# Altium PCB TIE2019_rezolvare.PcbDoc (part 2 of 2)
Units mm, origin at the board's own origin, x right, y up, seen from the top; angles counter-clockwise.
Board outline 267 x 129 mm, 8 copper layers (Signal 1, GND/Signal 2, GND 3, Signal 4, GND, Power/Signal 6, GND 7, Signal 8), stack 1.597 mm thick; 97 components, 82 nets, 657 pads, 352 vias.
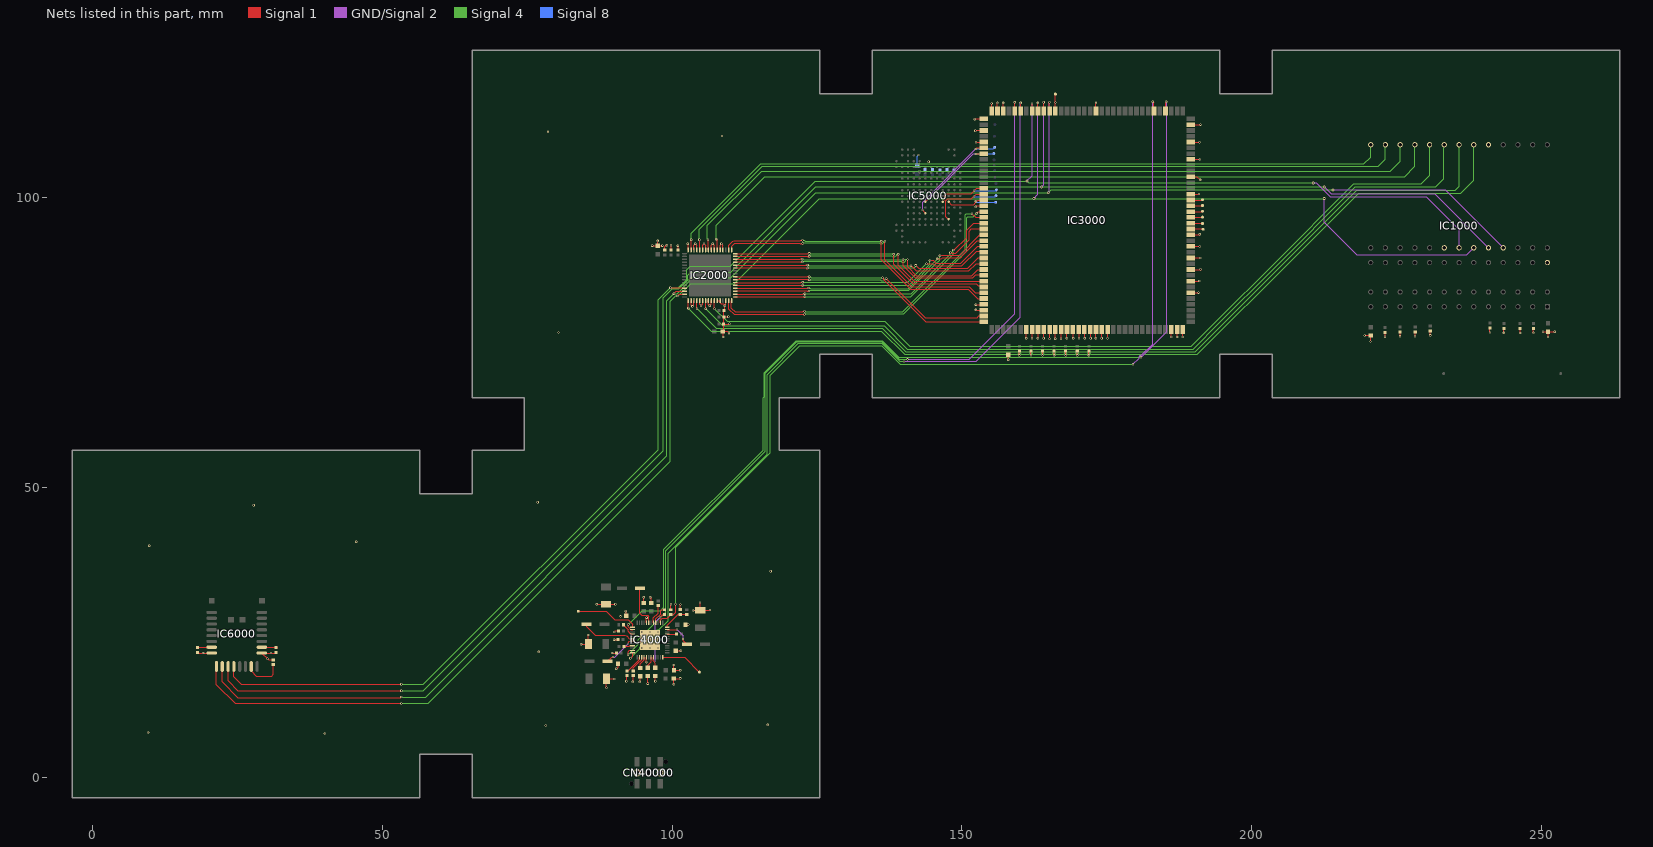
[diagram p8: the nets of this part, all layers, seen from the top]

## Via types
v1: diameter 0.4, hole 0.2, Signal 1 to Signal 8, 276 vias
v2: diameter 0.6, hole 0.3, Signal 1 to Signal 8, 49 vias
v3: diameter 0.325, hole 0.125, Signal 1 to GND/Signal 2, 9 vias
v4: diameter 0.5, hole 0.2, GND/Signal 2 to GND 7, 9 vias
v5: diameter 0.4, hole 0.2, Signal 1 to Signal 8, tented both sides, 9 vias

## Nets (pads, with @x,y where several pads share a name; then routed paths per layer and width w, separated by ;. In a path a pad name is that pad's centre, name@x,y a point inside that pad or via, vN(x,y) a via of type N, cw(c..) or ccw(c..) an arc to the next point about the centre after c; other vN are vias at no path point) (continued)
eMMC_DATA5: IC3000.83 IC5000.K8 TP_D5.1 | length 12.4
  Signal 1 w0.09: IC5000.K8@146.7,99.35 147.125,99.775 147.125,100.5 147.35,100.725 151.625,100.725 152.12,101.22 v1@152.123,101.223 ; v1(152.095,101.25) v1@152.123,101.223 ; IC3000.83@153.775,101.65 152.55,101.65 v1@152.123,101.223
  Signal 8 w0.09: v1(152.095,101.25) 152.095,101.244 155.778,101.244 TP_D5.1@155.931,101.397
eMMC_DATA6: IC3000.84 IC5000.N9 TP_D6.1 | length 14.2
  Signal 1 w0.09: IC5000.N9@147.7,96.35 147.25,96.8 147.25,99.55 147.525,99.825 151.65,99.825 152.475,100.65 IC3000.84@153.775,100.65
  Signal 8 w0.09: v1(152.07,100.254) 155.727,100.254 TP_D6.1@155.88,100.406
eMMC_DATA7: IC3000.85 IC5000.K9 TP_D7.1 | length 10.4
  Signal 1 w0.09: IC5000.K9@147.7,99.35 148.2,98.85 152.025,98.85 152.4,99.225 152.4,99.263 v1@152.493,99.357 ; v1(152.4,99.45) v1@152.493,99.357 ; IC3000.85@153.775,99.65 152.787,99.65 v1@152.493,99.357
  Signal 8 w0.09: v1(152.4,99.45) 152.4,99.263 TP_D7.1@155.829,99.263
eMMC_DS: IC3000.77 IC5000.K5 TP_DS.1 | length 16.6
  Signal 1 w0.09: IC5000.K5@143.7,99.35 v3(144.15,99.8) ; v1@152.35,107.6 152.4,107.65 IC3000.77@153.775,107.65
  GND/Signal 2 w0.09: v3(144.15,99.8) 151.95,107.6 v1@152.35,107.6
  Signal 8 w0.09: v1(152.4,107.594) 155.423,107.594 TP_DS.1@155.499,107.671
eMMC_RST: IC3000.76 IC5000.M5 TP_RST.1 | length 20
  Signal 1 w0.09: v3(143.2,97.9) 143.2,97.85 IC5000.M5@143.7,97.35 ; v1@152.4,108.5 152.55,108.65 IC3000.76@153.775,108.65
  GND/Signal 2 w0.09: v3(143.2,97.9) 143.2,99.3 v1@152.4,108.5
  Signal 8 w0.09: v1(152.4,108.458) 155.372,108.458 TP_RST.1@155.651,108.737
FRAME_CLK_N: IC2000.24 IC3000.106 | length 46.3
  Signal 1 w0.2: IC2000.24@110.899,86.415 110.934,86.38 110.954,86.4 123.33,86.4 123.43,86.5 123.65,86.5 v1(123.65,86.4) ; v1(136.3,86.235) 136.52,86.015 136.52,85.922 143.772,78.67 153.755,78.67 IC3000.106@153.775,78.65
  Signal 4 w0.09: v1(123.65,86.4) 123.675,86.375 123.847,86.375 123.987,86.235 v1(136.3,86.235)
FRAME_CLK_P: IC2000.23 IC3000.105 | length 46.1
  Signal 1 w0.2: IC2000.23@110.899,85.915 110.934,85.95 111.113,85.95 111.123,85.96 111.388,85.96 111.398,85.97 123.33,85.97 123.43,85.87 123.65,85.87 v1(123.65,85.9) ; v1(136.95,86.1) 143.7,79.35 152.625,79.35 152.925,79.65 IC3000.105@153.775,79.65
  Signal 4 w0.09: v1(123.65,85.9) 123.675,85.925 123.844,85.925 123.854,85.915 135.948,85.915 136.103,85.76 136.497,85.76 136.775,86.038 136.775,86.1 v1(136.95,86.1)
GND: C1001.1 C1002.1 C1003.1 C1004.1 C1005.1 C1101.1 C1102.1 C1103.1 C1104.1 C1105.1 C2001.1 C2002.1 C2003.1 C2004.1 C2101.1 C2102.1 C2103.1 C2104.1 C3000.2 C3001.2 C3002.2 C3003.2 C3004.2 C3005.2 C3006.2 C3007.2 C4001.1 C4002.1 C4003.1 C4004.2 C4005.2 C4006.1 C4007.1 C4008.1 C4009.1 C4010.2 C4011.1 C4012.2 C4013.1 C4014.2 C4015.1 C4016.2 C4017.1 C4019.1 C5001.2 C5002.2 C5003.2 C5004.1 C5005.1 C5006.1 C6001.1 C6002.1 C6003.1 CN40000.1 CN40000.3 IC1000.D1 IC1000.E8 IC1000.M5 IC2000.2 IC2000.3 IC2000.5 IC2000.6 IC2000.8 IC2000.9 IC2000.11 IC2000.12 IC2000.14 IC2000.36 IC2000.37 IC2000.39 IC2000.40 IC2000.42 IC2000.43 IC2000.45 IC2000.46 IC2000.48 IC3000.6 IC3000.8 IC3000.10 IC3000.12 IC3000.14 IC3000.16 IC3000.23 IC3000.26 IC3000.29 IC3000.32 IC3000.35 IC3000.52 IC3000.59 IC3000.68 IC3000.69 IC3000.70 IC3000.71 IC3000.73 IC3000.75 IC3000.86 IC3000.103 IC3000.104 IC3000.113 IC3000.114 IC3000.115 IC3000.116 IC3000.117 IC3000.118 IC3000.119 IC3000.120 IC3000.121 IC3000.122 IC3000.123 IC3000.124 IC3000.125 IC3000.126 IC3000.127 IC3000.138 IC3000.139 IC3000.140 IC4000.20 IC4000.41 IC4000.49 IC6000.8 IC6000.17 R4002.1 R4003.1 R4004.1 TH4000.1 TP3007.1 | length 154.5
  Signal 1 w0.1: C6003.1@18.3,21.58 18.38,21.5 v1(19.1,21.5) IC6000.8@20.575,21.5 ; C6002.1@31.2,20.32 30.38,20.32 v1(30.2,20.5) 29.225,21.475 IC6000.17@29.225,21.5 v1(30.8,21.5) 31.58,21.5 31.6,21.48 C6001.1@31.7,21.58 ; v1@84.4,23 84.45,23.05 C4013.1@85.575,23.05 v1@85.575,24.525 ; v1(87,29.9) C4017.1@88.6,29.9 v1@90.2,29.9 ; v1@88.675,15.525 C4011.1@88.675,17.05 v1@89.95,17.05 ; v1(89.647,21.5) C4009.1@90.38,21.5 ; v1@90,25.1 90.2,25.3 C4010.2@90.76,25.3 ; 90.2,23.8 C4012.2@90.86,23.8 ; v1(90.375,18.785) 90.675,19.085 C4002.1@90.675,19.65 ; C4019.1@91.96,27.8 C4019.1@92.06,27.9 v1@92.06,28.64 ; v1(92.109,16.619) 92.2,16.71 R4002.1@92.2,17.58 ; v1@93.3,16.5 R4003.1@93.3,17.59 ; v1@94.475,16.575 C4008.1@94.475,17.73 ; C4003.1@95.1,30.12 v1@95.1,31.1 ; v1(95.575,19.925) IC4000.41@95.575,20.75 ; IC4000.20@95.575,26.75 95.575,27.575 v1(95.6,27.6) ; v1@95.775,16.225 C4007.1@95.775,17.53 ; 95.775,16.425 v1@95.8,16.4 ; v1@96.2,31.1 96.4,30.9 C4016.2@96.4,30.12 ; v1(96.575,91.775) 96.61,91.74 C2001.1@97.525,91.74 ; v1@97.075,16.625 C4006.1@97.075,17.53 ; v1(97.5,92.6) 97.525,92.575 C2001.1@97.525,91.74 ; v1(98.325,91.775) 98.29,91.74 C2001.1@97.525,91.74 ; C2004.1@98.725,91.005 98.725,91.625 98.95,91.85 v1(99.1,91.85) ; R4004.1@99.775,28.96 v1@99.775,29.875 ; C2003.1@99.825,91.005 v1(99.825,91.85) ; v1@100.3,16.1 C4001.1@100.3,17.1 v1@101.4,17.1 ; v1@100.32,19.38 C4005.2@100.32,18.5 v1@101.4,18.5 ; C4004.2@100.6,21.88 v1@101.5,21.88 ; v1(101,91.775) 101.025,91.75 C2002.1@101.025,91.005 ; TH4000.1@101.4,29 v1@101.4,29.825 ; C4014.2@102.32,26.4 102.773,26.4 v1(102.773,26.419) ; v1(102.7,92.1) 102.774,92.026 IC2000.48@102.774,91.04 ; IC2000.2@103.274,82.29 103.274,81.526 v1(103.5,81.3) 103.774,81.574 IC2000.3@103.774,82.29 ; v1(103.627,28.819) 103.627,28.85 C4015.1@104.875,28.85 ; IC2000.46@103.774,91.04 103.774,91.874 v1(104,92.1) 104.274,91.826 IC2000.45@104.274,91.04 ; IC2000.5@104.774,82.29 104.774,81.626 v1(105,81.4) 105.274,81.674 IC2000.6@105.274,82.29 ; v1@104.875,30.125 C4015.1@104.875,28.85 ; IC2000.43@105.274,91.04 105.274,91.874 v1(105.5,92.1) 105.774,91.826 IC2000.42@105.774,91.04 ; IC2000.8@106.274,82.29 106.274,81.626 v1(106.5,81.4) 106.774,81.674 IC2000.9@106.774,82.29 ; v1@106.55,28.85 C4015.1@104.875,28.85 ; IC2000.40@106.774,91.04 106.774,91.874 v1(107,92.1) 107.274,91.826 IC2000.39@107.274,91.04 ; IC2000.11@107.774,82.29 IC2000.12@108.274,82.29 108.274,81.903 108.462,81.715 108.849,81.715 109.1,81.465 v1(109.1,81.4) ; IC2000.37@108.274,91.04 108.274,91.874 v1(108.5,92.1) 108.774,91.826 IC2000.36@108.774,91.04 ; v1(108.8,76) 108.8,76.895 C2101.1@108.72,76.975 ; IC2000.14@109.274,82.29 109.274,81.574 109.132,81.432 v1(109.1,81.4) ; v1(109.7,79.5) 109.675,79.475 C2103.1@108.92,79.475 ; v1(109.829,76.689) 109.543,76.975 C2101.1@108.72,76.975 ; v1(109.9,78.3) 109.857,78.257 C2102.1@108.901,78.257 ; v1@152.25,111.65 IC3000.73@153.775,111.65 ; v1@152.3,113.6 152.35,113.65 IC3000.71@153.775,113.65 ; v1(152.384,98.46) 152.574,98.65 IC3000.86@153.775,98.65 ; v1(152.4,80.7) 152.45,80.65 IC3000.104@153.775,80.65 ; v1(152.4,81.6) 153.725,81.6 IC3000.103@153.775,81.65 ; v1(152.424,109.605) 152.424,109.624 152.45,109.65 IC3000.75@153.775,109.65 ; IC3000.70@155.125,115 v1@155.125,116.275 ; v1@156.1,116.4 156.125,116.375 IC3000.69@156.125,115 ; IC3000.68@157.125,115 v1@157.125,116.375 ; v1(158,72.1) C3000.2@158,72.96 ; v1(159.9,72.845) C3001.2@159.9,73.58 ; v1(161.1,75.8) 161.125,75.825 IC3000.113@161.125,77.3 ; v1(161.9,72.845) C3002.2@161.9,73.58 ; v1(162.1,75.8) 162.125,75.825 IC3000.114@162.125,77.3 ; v1(163.1,75.8) 163.125,75.825 IC3000.115@163.125,77.3 ; v1(163.9,72.845) C3003.2@163.9,73.58 ; v1(164.1,75.8) 164.125,75.825 IC3000.116@164.125,77.3 ; v1(165.1,75.7) 165.125,75.725 IC3000.117@165.125,77.2 ; v1(165.9,72.845) C3004.2@165.9,73.58 ; v1(166.1,75.7) 166.125,75.725 IC3000.118@166.125,77.2 ; IC3000.59@166.125,115 166.125,117.925 TP3007.1@166.127,117.927 ; v1(167.1,75.7) 167.125,75.725 IC3000.119@167.125,77.2 ; v1(167.9,72.845) C3005.2@167.9,73.58 ; v1(168.1,75.8) 168.125,75.825 IC3000.120@168.125,77.3 ; v1(169.2,75.8) 169.225,75.825 IC3000.121@169.225,77.3 ; v1(169.9,72.845) C3006.2@169.9,73.58 ; v1(170.2,75.8) 170.225,75.825 IC3000.122@170.225,77.3 ; v1(171.2,75.8) 171.225,75.825 IC3000.123@171.225,77.3 ; v1(171.9,72.845) C3007.2@171.9,73.58 ; v1(172.2,75.8) 172.225,75.825 IC3000.124@172.225,77.3 ; v1(173.1,75.8) 173.125,75.825 IC3000.125@173.125,77.3 ; v1@173.1,116.4 173.125,116.375 IC3000.52@173.125,115 ; v1(174.1,75.8) 174.125,75.825 IC3000.126@174.125,77.3 ; v1(175.1,75.8) 175.125,75.825 IC3000.127@175.125,77.3 ; v1(186.124,76.005) 186.125,76.006 IC3000.138@186.125,77.3 ; v1(187.125,76.025) IC3000.139@187.125,77.3 ; v1(188.1,76) 188.125,76.025 IC3000.140@188.125,77.3 ; IC3000.6@189.475,83.65 v1@190.85,83.65 ; IC3000.8@189.475,85.65 191.05,85.65 v1@191.049,85.651 ; IC3000.10@189.475,87.65 191.25,87.65 v1@191.24,87.66 ; IC3000.12@189.475,89.65 v1@191.15,89.65 ; IC3000.14@189.475,91.65 v1@191.15,91.65 ; IC3000.16@189.475,93.65 v1@191.05,93.65 ; IC3000.23@189.475,100.65 190.85,100.65 v1(190.9,100.7) ; IC3000.26@189.475,103.65 190.55,103.65 191.075,103.125 v1(191.1,103.125) ; IC3000.29@189.475,106.65 v1(191.05,106.65) ; IC3000.32@189.475,109.65 190.95,109.65 v1(191,109.6) ; IC3000.35@189.475,112.65 v1(191.15,112.65) ; v1(219.475,76.275) 220.495,76.275 C1005.1@220.5,76.28 220.5,75.275 v1@220.475,75.25 ; v1(222.975,76.075) 223,76.1 C1004.1@223,76.78 ; C1003.1@225.6,76.88 225.6,76.04 v1@225.623,76.017 ; v1(228.175,76.15) 228.2,76.175 C1002.1@228.2,76.88 ; v1(230.8,76.3) C1001.1@230.8,77.06 ; v1(241.1,76.8) C1104.1@241.1,77.48 ; v1@243.483,76.713 v1(243.5,76.73) C1103.1@243.5,77.48 ; v1(246.3,76.7) C1102.1@246.3,77.48 ; v1(248.6,76.725) C1101.1@248.6,77.48 ; v1(250.235,76.935) C1105.1@251.118,76.935 ; v1(251.118,76.018) C1105.1@251.118,76.935 ; v1(252.265,76.935) C1105.1@251.118,76.935 ; C2101.1@108.72,76.975 108.901,77.156 C2102.1@108.901,78.257 ; C2102.1@108.901,78.257 108.92,78.277 C2103.1@108.92,79.475 ; C2103.1@108.92,79.475 108.92,80.655 108.9,80.675 109.042,80.817 109.042,81.342 v1(109.1,81.4)
  Signal 8 w0.09: C5001.2@142.3,105.59 142.3,107.2 v1(142.5,107.4)
  other v1: 40.1,7.6 9.6,7.8 78.2,9 116.5,9.1 88.677,15.516 100.309,16.119 95.809,16.219 93.209,16.519 94.409,16.519 97.109,16.619 90.009,17.019 101.409,17.119 101.409,18.519 100.309,19.419 77,21.7 101.509,21.899 84.309,23.019 90,23.8 85.509,24.619 90.009,25.119 91.109,27.819 92.009,28.719 106.538,28.928 101.434,29.869 90.209,29.919 99.809,29.919 104.809,30.219 95.109,31.119 96.209,31.119 117,35.6 9.8,40 45.5,40.7 27.8,47 76.8,47.5 220.5,75.25 225.575,76.125 80.4,76.8 190.815,83.668 190.96,85.687 191.163,87.695 191.127,89.635 191.027,91.635 191.027,93.735 144.25,106.25 108.6,110.7 78.6,111.4 152.324,111.605 152.224,113.605 155.124,116.305 156.124,116.405 157.107,116.408 173.124,116.405 166.149,116.468
  other v5: 94.775,22.35 96.175,22.35 97.575,22.35 94.775,23.75 96.175,23.75 97.575,23.75 94.775,25.15 96.175,25.15 97.575,25.15
IMGSEN_DATA0: IC1000.M6 IC2000.1 | length 159.6
  Signal 1 w0.1: IC2000.1@102.774,82.29 102.774,81.026 v1(102.8,81)
  Signal 4 w0.07: v1(102.8,81) 106.773,77.027 125.5,77.027 134.5,77.027 136.079,77.027 140.095,73.011 159.592,73.011 159.761,73.18 160.039,73.18 160.208,73.011 161.592,73.011 161.761,73.18 162.039,73.18 162.208,73.011 163.592,73.011 163.761,73.18 164.039,73.18 164.208,73.011 165.592,73.011 165.761,73.18 166.039,73.18 166.208,73.011 167.592,73.011 167.761,73.18 168.039,73.18 168.208,73.011 169.592,73.011 169.761,73.18 170.039,73.18 170.208,73.011 171.592,73.011 171.761,73.18 172.039,73.18 172.208,73.011 190.613,73.011 194.5,76.898 203.5,85.898 218.415,100.813 236.017,100.813 238.3,103.096 238.3,106.474 IC1000.M6@238.3,109.18
IMGSEN_DATA1: IC1000.M7 IC2000.4 | length 154.9
  Signal 1 w0.1: IC2000.4@104.274,82.29 104.274,80.926 v1(104.3,80.9)
  Signal 4 w0.07: v1(104.3,80.9) 107.64,77.56 125.5,77.56 134.5,77.56 136.232,77.56 140.298,73.494 190.257,73.494 194.5,77.736 203.5,86.736 218.135,101.371 235.077,101.371 235.76,102.054 235.76,105.159 IC1000.M7@235.76,109.18
IMGSEN_DATA2: IC1000.M8 IC2000.7 | length 149.7
  Signal 1 w0.1: IC2000.7@105.774,82.29 105.774,80.926 v1(105.8,80.9)
  Signal 4 w0.07: v1(105.8,80.9) 108.772,77.928 109.324,77.928 109.598,77.928 110.002,77.928 125.5,77.928 134.5,77.928 136.575,77.928 140.603,73.9 189.876,73.9 194.5,78.524 203.5,87.524 217.881,101.905 231.75,101.905 233.147,103.302 233.147,109.107 IC1000.M8@233.22,109.18
IMGSEN_DATA3: IC1000.M9 IC2000.10 | length 145.1
  Signal 1 w0.1: IC2000.10@107.274,82.29 107.274,80.926 v1(107.3,80.9)
  Signal 4 w0.07: v1(107.3,80.9) 109.5,78.7 109.904,78.7 110.3,78.7 125.5,78.7 134.5,78.7 136.692,78.7 141.009,74.383 189.572,74.383 194.5,79.311 203.5,88.311 217.602,102.413 229.26,102.413 230.734,103.886 230.734,109.126 IC1000.M9@230.68,109.18
IMGSEN_DATA4: IC1000.M10 IC2000.38 | length 132.8
  Signal 1 w0.1: v1(107.6,92.9) 107.774,92.726 IC2000.38@107.774,91.04
  Signal 4 w0.1: v1(107.6,92.9) 107.575,92.925 107.575,95.281 115.994,103.7 125.5,103.7 134.5,103.7 140.555,103.7 140.845,103.7 141.555,103.7 141.845,103.7 142.555,103.7 142.845,103.7 142.959,103.7 143.544,103.7 143.555,103.7 143.845,103.7 144.555,103.7 144.845,103.7 145.555,103.7 145.845,103.7 194.5,103.7 203.5,103.7 226.357,103.7 228.14,105.483 IC1000.M10@228.14,109.18
IMGSEN_DATA5: IC1000.M11 IC2000.41 | length 131.2
  Signal 1 w0.1: v1(106.2,92.8) 106.274,92.726 IC2000.41@106.274,91.04
  Signal 4 w0.1: v1(106.2,92.8) 106.1,92.9 106.1,95.254 115.496,104.65 125.5,104.65 134.5,104.65 142.505,104.65 142.555,104.7 142.845,104.7 142.895,104.65 194.5,104.65 203.5,104.65 223.878,104.65 225.6,106.372 IC1000.M11@225.6,109.18
IMGSEN_DATA6: IC1000.M12 IC2000.44 | length 129.5
  Signal 1 w0.1: v1(104.7,92.8) 104.774,92.726 IC2000.44@104.774,91.04
  Signal 4 w0.1: v1(104.7,92.8) 104.65,92.85 104.65,94.592 115.519,105.461 125.5,105.461 134.5,105.461 194.5,105.461 203.5,105.461 221.818,105.461 223.06,106.703 IC1000.M12@223.06,109.18
IMGSEN_DATA7: IC1000.M13 IC2000.47 | length 127.7
  Signal 1 w0.1: IC2000.47@103.274,91.04 103.274,91.799 103.289,91.814 103.28,91.822 103.28,92.78 v1(103.3,92.8)
  Signal 4 w0.1: v1(103.3,92.8) 103.28,92.82 103.28,93.882 115.298,105.9 125.5,105.9 134.5,105.9 144.105,105.9 144.395,105.9 194.5,105.9 203.5,105.9 219.356,105.9 220.52,107.064 IC1000.M13@220.52,109.18
LVDS_D0_N: IC2000.16 IC3000.88 | length 56
  Signal 1 w0.2: IC2000.16@110.274,82.29 110.239,82.255 110.239,81 110.864,80.375 122.505,80.375 122.605,80.475 122.825,80.475 v1(122.825,80.445) ; v1(151.725,97.27) 152.345,96.65 IC3000.88@153.775,96.65
  Signal 4 w0.09: v1(122.825,80.445) 122.915,80.355 139.8,80.355 150.55,91.105 150.55,97.083 150.737,97.27 v1(151.725,97.27)
LVDS_D0_P: IC2000.15 IC3000.87 | length 56.6
  Signal 1 w0.2: IC2000.15@109.774,82.29 109.809,82.255 109.809,80.822 110.686,79.945 122.505,79.945 122.605,79.845 122.825,79.845 v1(122.825,79.945) ; v1(152.55,97.375) 152.825,97.65 IC3000.87@153.775,97.65
  Signal 4 w0.09: v1(122.825,79.945) 122.915,80.035 139.933,80.035 150.8,90.902 150.8,96.6 150.97,96.77 151.945,96.77 v1(152.55,97.375)
LVDS_D1_N: IC2000.18 IC3000.90 | length 48.8
  Signal 1 w0.2: IC2000.18@110.899,83.415 110.934,83.38 110.979,83.425 122.58,83.425 122.68,83.525 122.9,83.525 v1(122.9,83.495) ; v1(148,90.557) 148.053,90.503 148.175,90.625 148.344,90.457 148.915,90.457 149.009,90.55 151.23,92.771 151.23,94.275 151.605,94.65 IC3000.90@153.775,94.65
  Signal 4 w0.09: v1(122.9,83.495) 125.5,83.495 134.5,83.495 141.23,83.495 148,90.265 148,90.45 v1(148,90.557)
LVDS_D1_P: IC2000.17 IC3000.89 | length 49.6
  Signal 1 w0.2: IC2000.17@110.899,82.915 110.934,82.95 111.113,82.95 111.123,82.96 111.388,82.96 111.423,82.995 122.58,82.995 122.68,82.895 122.9,82.895 v1(122.9,82.995) ; v1(148.525,91.025) 148.7,91.025 150.8,93.125 150.8,94.453 151.997,95.65 152.175,95.65 IC3000.89@153.775,95.65
  Signal 4 w0.09: v1(122.9,82.995) 125.5,82.995 134.5,82.995 141.182,82.995 148.475,90.288 148.475,90.647 148.311,90.811 v1(148.525,91.025)
LVDS_D2_N: IC2000.20 IC3000.92 | length 46.5
  Signal 1 w0.2: IC2000.20@110.899,84.415 110.934,84.38 110.979,84.425 123.33,84.425 123.396,84.491 123.575,84.491 v1(123.575,84.459) ; v1(145.727,89.493) 145.98,89.495 146.42,89.495 146.651,89.727 149.76,89.727 150.208,90.175 152.683,92.65 IC3000.92@153.775,92.65
  Signal 4 w0.09: v1(123.575,84.459) 123.598,84.436 123.812,84.436 123.878,84.37 125.5,84.37 134.5,84.37 140.725,84.37 145.775,89.42 145.775,89.446 v1(145.727,89.493)
LVDS_D2_P: IC2000.19 IC3000.91 | length 47.5
  Signal 1 w0.2: IC2000.19@110.899,83.915 110.934,83.95 111.113,83.95 111.123,83.96 111.388,83.96 111.423,83.995 123.255,83.995 123.355,83.895 123.615,83.895 v1(123.615,83.961) ; v1(146.2,90.025) 146.332,90.157 149.582,90.157 153.075,93.65 IC3000.91@153.775,93.65
  Signal 4 w0.09: v1(123.615,83.961) 123.704,84.05 140.858,84.05 145.826,89.018 145.924,89.018 146.202,89.297 146.202,89.69 146.2,89.692 v1(146.2,90.025)
LVDS_D3_N: IC2000.22 IC3000.94 | length 45.6
  Signal 1 w0.2: IC2000.22@110.899,85.415 110.934,85.38 110.954,85.4 122.205,85.4 122.305,85.5 122.525,85.5 v1(122.525,85.47) ; v1(143.875,88.65) 144.992,88.65 145.196,88.446 145.322,88.32 150.003,88.32 150.129,88.446 152.529,90.846 153.579,90.846 IC3000.94@153.775,90.65
  Signal 4 w0.09: v1(122.525,85.47) 140.695,85.47 v1(143.875,88.65)
LVDS_D3_P: IC2000.21 IC3000.93 | length 46.5
  Signal 1 w0.2: IC2000.21@110.899,84.915 110.934,84.95 111.113,84.95 111.123,84.96 111.388,84.96 111.398,84.97 122.205,84.97 122.305,84.87 122.525,84.87 v1(122.525,84.97) ; v1(144.472,89.217) 145.033,89.217 145.5,88.75 149.825,88.75 152.725,91.65 IC3000.93@153.775,91.65
  Signal 4 w0.09: v1(122.525,84.97) 125.5,84.97 134.5,84.97 140.87,84.97 144.45,88.55 v1@144.45,89.175
LVDS_D4_N: IC2000.28 IC3000.96 | length 43.9
  Signal 1 w0.2: IC2000.28@110.899,88.415 110.934,88.38 123.086,88.38 123.155,88.45 123.375,88.45 v1(123.375,88.42) ; v1(141.223,88.33) 142.133,87.42 151.203,87.42 152.433,88.65 IC3000.96@153.775,88.65
  Signal 4 w0.09: v1(123.375,88.42) 123.4,88.395 123.572,88.395 123.637,88.33 134.5,88.33 v1(141.223,88.33)
LVDS_D4_P: IC2000.27 IC3000.95 | length 44.3
  Signal 1 w0.2: IC2000.27@110.899,87.915 110.934,87.95 123.025,87.95 123.155,87.82 123.375,87.82 v1(123.375,87.92) ; v1(142.025,88.375) 142.55,87.85 151.025,87.85 152.825,89.65 IC3000.95@153.775,89.65
  Signal 4 w0.09: v1(123.375,87.92) 123.4,87.945 123.572,87.945 125.5,87.945 134.5,87.945 141.745,87.945 142.025,88.225 v1(142.025,88.375)
LVDS_D5_N: IC2000.30 IC3000.98 | length 45.2
  Signal 1 w0.2: IC2000.30@110.899,89.415 110.934,89.38 110.954,89.4 122.13,89.4 122.23,89.5 122.45,89.5 v1(122.45,89.47) ; v1(139.85,89.38) 139.85,88.317 141.846,86.321 141.972,86.195 151.853,86.195 151.979,86.321 152.404,86.746 153.679,86.746 IC3000.98@153.775,86.65
  Signal 4 w0.09: v1(122.45,89.47) 122.475,89.445 122.647,89.445 122.712,89.38 v1(139.85,89.38)
LVDS_D5_P: IC2000.29 IC3000.97 | length 45.8
  Signal 1 w0.2: IC2000.29@110.899,88.915 110.934,88.95 111.113,88.95 111.123,88.96 111.388,88.96 111.398,88.97 122.13,88.97 122.23,88.87 122.45,88.87 v1(122.45,88.97) ; v1(140.625,89.4) 140.625,88.15 142.15,86.625 151.675,86.625 152.7,87.65 IC3000.97@153.775,87.65
  Signal 4 w0.09: v1(122.45,88.97) 122.475,88.995 122.647,88.995 122.712,89.06 139.498,89.06 139.653,88.905 140.047,88.905 140.325,89.183 140.325,89.4 v1(140.625,89.4)
LVDS_D6_N: IC2000.32 IC3000.100 | length 46.4
  Signal 1 w0.2: IC2000.32@110.899,90.415 110.934,90.38 123.359,90.38 123.453,90.475 123.65,90.475 v1(123.65,90.444) ; v1(138.25,90.305) 138.25,88.542 141.617,85.175 152.475,85.175 152.825,84.825 153.6,84.825 IC3000.100@153.775,84.65
  Signal 4 w0.09: v1(123.65,90.444) 123.674,90.42 123.87,90.42 123.935,90.355 134.5,90.355 138.2,90.355 v1(138.25,90.305)
LVDS_D6_P: IC2000.31 IC3000.99 | length 46.5
  Signal 1 w0.2: IC2000.31@110.899,89.915 110.934,89.95 123.325,89.95 123.43,89.845 123.673,89.845 v1(123.673,89.945) ; v1(139.025,90.3) 139.025,88.375 141.75,85.65 IC3000.99@153.775,85.65
  Signal 4 w0.09: v1(123.673,89.945) 123.697,89.969 123.847,89.969 123.912,90.035 134.5,90.035 137.848,90.035 138.053,89.83 138.447,89.83 138.725,90.108 138.725,90.3 v1(139.025,90.3)
LVDS_D7_N: IC2000.34 IC3000.102 | length 51.2
  Signal 1 w0.2: IC2000.34@109.774,91.04 109.774,91.808 110.496,92.529 110.622,92.655 122.124,92.655 122.211,92.742 122.458,92.742 v1(122.5,92.7) ; v1(136.075,92.539) 136.075,89.367 141.172,84.27 151.08,84.27 152.7,82.65 IC3000.102@153.775,82.65
  Signal 4 w0.09: v1(122.5,92.7) 122.822,92.7 122.983,92.539 125.5,92.539 134.5,92.539 v1(136.075,92.539)
LVDS_D7_P: IC2000.33 IC3000.101 | length 50.4
  Signal 1 w0.2: IC2000.33@110.274,91.04 110.274,91.699 110.8,92.225 122.025,92.225 122.105,92.145 122.514,92.145 v1(122.526,92.158) ; v1(136.725,92.525) 136.725,89.325 141.35,84.7 151.258,84.7 152.308,83.65 IC3000.101@153.775,83.65
  Signal 4 w0.09: v1(122.526,92.158) 122.526,92.226 122.544,92.244 125.5,92.244 135.698,92.244 135.878,92.064 136.272,92.064 136.55,92.342 136.55,92.525 v1(136.725,92.525)
NetC4006_2: C4006.2 IC4000.44 R4005.2 | length 11
  Signal 1 w0.1: IC4000.44@96.775,20.75 96.775,20.125 97,19.9 v3(97.1,19.9) C4006.2@97.1,18.995 ; v3(97.9,27.6) 98.34,28.04 98.34,28.14 R4005.2@98.675,28.14
  GND/Signal 2 w0.1: v3(97.1,19.9) 97.1,26.8 v3(97.9,27.6)
NetC4007_2: C4007.2 IC4000.43 | length 1.8
  Signal 1 w0.1: C4007.2@95.775,19.17 95.8,19.195 95.8,19.4 96.375,19.975 IC4000.43@96.375,20.75
NetC4008_2: C4008.2 IC4000.40 | length 1.9
  Signal 1 w0.1: C4008.2@94.475,19.17 94.475,19.675 95.175,20.375 IC4000.40@95.175,20.75
NetC6001_2: C6001.2 IC6000.18 | length 2.7
  Signal 1 w0.1: IC6000.18@29.225,22.5 31.8,22.5 C6001.2@31.914,22.386
NetC6002_2: C6002.2 IC6000.15 | length 6.8
  Signal 1 w0.1: IC6000.15@27.4,19.175 27.4,18.4 28.3,17.5 30.9,17.5 31.2,17.8 C6002.2@31.2,19.48
NetC6003_2: C6003.2 IC6000.7 | length 2.3
  Signal 1 w0.1: C6003.2@18.3,22.42 18.38,22.5 IC6000.7@20.575,22.5
NetIC3000_17: IC3000.17 TP3000.1 | length 2.1
  Signal 1 w0.09: IC3000.17@189.475,94.65 191.55,94.65 TP3000.1@191.6,94.6
NetIC3000_18: IC3000.18 TP3001.1 | length 2
  Signal 1 w0.1: IC3000.18@189.475,95.65 191.45,95.65 TP3001.1@191.5,95.6
NetIC3000_19: IC3000.19 TP3002.1 | length 2.4
  Signal 1 w0.1: IC3000.19@189.475,96.65 191.65,96.65 191.7,96.7 TP3002.1@191.5,96.7
NetIC3000_20: IC3000.20 TP3003.1 | length 2
  Signal 1 w0.09: IC3000.20@189.475,97.65 191.45,97.65 TP3003.1@191.5,97.7
NetIC3000_21: IC3000.21 TP3004.1 | length 2
  Signal 1 w0.1: IC3000.21@189.475,98.65 191.45,98.65 TP3004.1@191.5,98.7
NetIC3000_22: IC3000.22 TP3005.1 | length 2
  Signal 1 w0.1: IC3000.22@189.475,99.65 191.45,99.65 TP3005.1@191.5,99.7
NetIC4000_11: IC4000.11 L4003.1 | length 4.9
  Signal 1 w0.1: IC4000.11@99.175,25.55 v3(100.85,25.55) ; v3(101.9,23.9) 101.9,23.65 L4003.1@102.55,23
  GND/Signal 2 w0.1: v3(100.85,25.55) 101.9,24.5 v3(101.9,23.9)
NetIC4000_12: IC4000.12 R4001.1 TH4000.2 | length 4.5
  Signal 1 w0.1: IC4000.12@99.175,25.95 99.175,26.275 101.08,28.18 TH4000.2@101.4,28.18 102.485,28.18 R4001.1@102.525,28.14
NetIC4000_16: IC4000.16 R4005.1 | length 3.1
  Signal 1 w0.1: IC4000.16@97.175,26.75 97.175,27.375 98,28.2 98,28.8 98.16,28.96 R4005.1@98.675,28.96
NetIC4000_19: IC4000.19 L4004.1 | length 7.2
  Signal 1 w0.1: L4004.1@94.45,32.7 94.45,28.35 94.75,28.05 95.75,28.05 95.8,28 96,27.8 96,26.775 IC4000.19@95.975,26.75
NetIC4000_25: IC4000.25 TP4010.1 | length 10.8
  Signal 1 w0.1: TP4010.1@83.8,28.7 88.6,28.7 90.1,27.2 92.4,27.2 93.175,26.425 IC4000.25@93.175,25.95
NetIC4000_30: IC4000.30 L4002.1 | length 9.2
  Signal 1 w0.1: L4002.1@85.25,26.5 85.25,26.05 86.7,24.6 91.955,24.6 92.105,24.45 92.15,24.45 92.65,23.95 IC4000.30@93.175,23.95
NetIC4000_31: IC4000.31 L4000.1 | length 5.9
  Signal 1 w0.1: L4000.1@88.825,20.05 89.575,20.8 v3(89.8,20.8) ; v3(92.4,23.1) 92.4,23.3 92.65,23.55 IC4000.31@93.175,23.55
  GND/Signal 2 w0.1: v3(89.8,20.8) 90.1,20.8 v3(92.4,23.1)
NetIC4000_38: IC4000.38 R4002.2 | length 3.4
  Signal 1 w0.1: R4002.2@92.2,18.4 92.4,18.4 94.375,20.375 IC4000.38@94.375,20.75
NetIC4000_39: IC4000.39 R4003.2 | length 3
  Signal 1 w0.1: R4003.2@93.3,18.41 93.3,18.957 93.95,19.607 94.038,19.695 94.095,19.695 94.775,20.375 IC4000.39@94.775,20.75
NetIC4000_48: IC4000.48 TP4011.1 | length 7.4
  Signal 1 w0.1: IC4000.48@98.375,20.75 102.15,20.75 TP4011.1@104.7,18.2
PMIC_CLK: IC3000.42 IC4000.14 R4004.2 | length 165.8
  Signal 1 w0.1: IC4000.14@97.975,26.75 97.975,27.175 98.3,27.5 99.135,27.5 R4004.2@99.775,28.14 100.24,28.14 100.6,28.5 v1(100.6,29.9) ; v1(182.924,116.605) 183.125,116.404 IC3000.42@183.125,115
  GND/Signal 2 w0.1: v1(179.5,71.3) 180.553,72.353 180.55,72.355 180.55,72.645 180.755,72.85 180.974,72.85 182.9,74.776 v1@182.9,116.6
  Signal 4 w0.1: v1(100.6,29.9) 100.6,39.724 116.9,56.024 116.9,69.4 122,74.5 136.2,74.5 139.4,71.3 v1(179.5,71.3)
PMIC_I1C_SCL: IC3000.66 IC4000.35 | length 147.6
  Signal 1 w0.09: v1(92.4,21.2) 92.4,21.716 92.5,21.816 92.63,21.946 92.946,21.946 92.95,21.95 IC4000.35@93.175,21.95 ; v1(159.124,116.505) IC3000.66@159.125,115 IC3000.66@159.125,115
  GND/Signal 2 w0.09: v1(140.6,72.155) 140.6,72.2 151.3,72.2 159.1,80 v1@159.1,116.5
  Signal 4 w0.09: v1(92.4,21.2) 94.2,23 94.2,23.8 98.9,28.5 98.9,39.1 116.1,56.3 116.1,56.5 116.1,65.5 116.1,69.8 121.5,75.2 125.5,75.2 134.5,75.2 135.6,75.2 135.9,75.2 136.169,75.2 139.169,72.2 140.6,72.2 v1(140.6,72.155)
PMIC_I1C_SDA: IC3000.65 IC4000.36 | length 149
  Signal 1 w0.09: v1(92.8,20.6) 93.175,20.975 IC4000.36@93.175,21.55 ; v1(160.124,116.405) IC3000.65@160.125,115 IC3000.65@160.125,115
  GND/Signal 2 w0.09: v1(140,71.8) 152.5,71.8 160.1,79.4 v1@160.1,116.4
  Signal 4 w0.09: v1(92.8,20.6) 94.43,22.23 94.43,22.493 94.632,22.695 94.895,22.695 95.83,23.63 95.83,23.893 96.032,24.095 96.295,24.095 97.23,25.03 97.23,25.293 97.432,25.495 97.695,25.495 99.3,27.1 99.3,38.7 116.4,55.8 116.4,69.5 121.8,74.9 125.5,74.9 134.5,74.9 136.2,74.9 139.3,71.8 v1(140,71.8)
PMIC_INT: IC3000.40 IC4000.26 | length 172.5
  Signal 1 w0.09: v1@92.4,26.381 92.4,26 92.85,25.55 IC4000.26@93.175,25.55 ; IC3000.40@185.125,115 185.125,116.506 v1(185.224,116.605)
  GND/Signal 2 w0.09: v1(180.9,72.5) 185.3,76.9 185.3,116.5 v1@185.2,116.6
  Signal 4 w0.09: v1(92.424,26.405) 94.819,28.8 98,28.8 98.6,29.4 98.6,39.4 115.7,56.5 115.7,65.5 115.91,65.71 115.91,69.879 121.421,75.39 136.11,75.39 136.247,75.39 139.137,72.5 v1(180.9,72.5)
SMPS1_FDBK: IC4000.33 R4006.1 | length 1.6
  Signal 1 w0.1: R4006.1@91.695,22.65 92.35,22.65 92.65,22.65 92.8,22.8 93.125,22.8 IC4000.33@93.175,22.75
SMPS2_FDBK: IC4000.28 R4007.1 | length 2.5
  Signal 1 w0.1: R4007.1@91.615,26.385 92.45,25.55 92.45,25.25 92.625,25.075 92.625,24.988 92.713,24.9 92.8,24.9 92.95,24.75 IC4000.28@93.175,24.75
SMPS3_FDBK: IC4000.9 R4008.1 | length 1.6
  Signal 1 w0.1: IC4000.9@99.175,24.75 R4008.1@100.785,24.75
SMPS4_FDBK: IC4000.17 R4009.1 | length 3.3
  Signal 1 w0.1: IC4000.17@96.775,26.75 96.775,27.575 97.6,28.4 R4009.1@97.6,29.69
SPI1_CLK: IC1000.E6 IC2000.63 IC3000.62 IC6000.9 | length 300.1
  Signal 1 w0.1: IC6000.9@21.4,19.175 21.4,16 24.6,12.8 v1(53.3,12.8) ; v1(100.9,83.1) 101.215,83.415 IC2000.63@102.149,83.415 ; v1(163.1,116.4) 163.1,115.025 IC3000.62@163.125,115
  GND/Signal 2 w0.1: v4(162.4,99.9) 163.1,100.6 v1(163.1,116.4) ; v4(212.5,99.9) 212.5,95.8 218.1,90.2 237.1,90.2 IC1000.E6@238.3,91.4
  Signal 4 w0.1: v1(53.3,12.8) 57.9,12.8 99.7,54.6 99.7,82.2 100.6,83.1 v1(100.9,83.1) 101.1,83.1 103.2,85.2 110.7,85.2 125.4,99.9 v4(162.4,99.9) v4(212.5,99.9)
SPI1_CS: IC1000.E7 IC2000.61 IC3000.63 IC6000.12 | length 289.8
  Signal 1 w0.1: IC6000.12@24.4,19.175 24.4,17.4 25.7,16.1 v1(53.3,16.1) ; v1(99.7,84.5) 102.065,84.5 IC2000.61@102.149,84.415 ; v1(162.1,116.3) 162.1,115.025 IC3000.63@162.125,115
  GND/Signal 2 w0.1: v4(161.202,102.931) 162.1,103.828 v1(162.1,116.3) ; v4(210.6,102.6) 211.1,102.6 213.5,100.2 230.1,100.2 235.76,94.54 IC1000.E7@235.76,91.4
  Signal 4 w0.1: v1(53.3,16.1) 57.1,16.1 97.6,56.6 97.6,82.4 v1(99.7,84.5) 101.1,84.5 102.5,85.9 102.5,87.6 103.1,88.2 110,88.2 124.701,102.901 v4@161.121,102.901 ; v4(161.202,102.931) 161.533,102.6 v4(210.6,102.6)
SPI1_MISO: IC1000.E4 IC2000.62 IC3000.60 IC6000.10 | length 300.3
  Signal 1 w0.1: IC6000.10@22.4,19.175 22.4,16.5 25.1,13.8 53.2,13.8 v1(53.3,13.9) ; v1(100.3,83.5) 100.715,83.915 IC2000.62@102.149,83.915 ; v1(165.1,116.5) 165.1,115.025 IC3000.60@165.125,115
  GND/Signal 2 w0.1: v4(164.9,100.9) 165.1,101.1 v1(165.1,116.5) ; v4(214,101.4) 233.38,101.4 IC1000.E4@243.38,91.4
  Signal 4 w0.1: v1(53.3,13.9) 57.5,13.9 99.1,55.5 99.1,82.3 v1(100.3,83.5) 100.9,83.5 103,85.6 103,86 103.2,86.2 110.1,86.2 124.8,100.9 v4(164.9,100.9) 165.4,101.4 v4(214,101.4)
SPI1_MOSI: IC1000.E5 IC3000.61 IC6000.11 | length 293.2
  Signal 1 w0.1: IC6000.11@23.4,19.175 23.4,16.7 25.1,15 v1(53.3,15) ; v1(164.1,116.5) 164.1,115.025 IC3000.61@164.125,115
  GND/Signal 2 w0.1: v4(163.7,101.9) 164.1,102.3 v1(164.1,116.5) ; v4(212.5,101.9) 213.7,100.7 231.54,100.7 IC1000.E5@240.84,91.4
  Signal 4 w0.1: v1(53.3,15) 57.1,15 98.5,56.4 98.5,82.8 100,84.3 101.183,84.3 102.7,85.817 102.7,86.7 103.2,87.2 110.1,87.2 124.8,101.9 v4(163.7,101.9) v4(212.5,101.9)
pads on no net: CN40000. IC1000.B1 IC1000.B2 IC1000.B3 IC1000.B4 IC1000.B5 IC1000.B6 IC1000.B7 IC1000.B8 IC1000.B9 IC1000.B10 IC1000.B11 IC1000.B12 IC1000.B13 IC1000.D4 IC1000.D5 IC1000.D6 IC1000.D8 IC1000.D10 IC1000.D12 IC1000.E1 IC1000.E2 IC1000.E3 IC1000.E9 IC1000.E10 IC1000.E11 IC1000.E12 IC1000.E13 IC1000.M1 IC1000.M2 IC1000.M3 IC1000.M4 IC2000. IC2000.13 IC2000.49 IC2000.51 IC2000.52 IC2000.53 IC2000.54 IC2000.55 IC2000.56 IC3000.1 IC3000.2 IC3000.3 IC3000.4 IC3000.5 IC3000.24 IC3000.25 IC3000.27 IC3000.28 IC3000.30 IC3000.31 IC3000.36 IC3000.43 IC3000.44 IC3000.45 IC3000.46 IC3000.47 IC3000.48 IC3000.49 IC3000.50 IC3000.51 IC3000.53 IC3000.54 IC3000.55 IC3000.56 IC3000.57 IC3000.58 IC3000.64 IC3000.67 IC3000.128 IC3000.129 IC3000.130 IC3000.131 IC3000.132 IC3000.133 IC3000.134 IC3000.135 IC3000.136 IC3000.137 IC4000.1 IC4000.2 IC4000.3 IC4000.4 IC4000.5 IC4000.6 IC4000.7 IC4000.13 IC4000.15 IC4000.21 IC4000.24 IC4000.27 IC4000.45 IC4000.47 IC5000.A1 IC5000.A2 IC5000.A3 IC5000.A9 IC5000.A10 IC5000.B1 IC5000.B2 IC5000.B3 IC5000.B10 IC5000.C0 IC5000.C2 IC5000.C3 IC5000.C4 IC5000.D0 IC5000.D1 IC5000.D2 IC5000.D3 IC5000.D4 IC5000.D5 IC5000.D6 IC5000.D7 IC5000.D8 IC5000.D9 IC5000.D10 IC5000.E1 IC5000.E2 IC5000.E3 IC5000.E5 IC5000.E6 IC5000.E7 IC5000.E8 IC5000.E9 IC5000.E10 IC5000.E11 IC5000.F1 IC5000.F10 IC5000.F11 IC5000.G2 IC5000.G3 IC5000.G4 IC5000.G5 IC5000.G6 IC5000.G7 IC5000.G8 IC5000.G9 IC5000.G10 IC5000.G11 IC5000.H1 IC5000.H2 IC5000.H4 IC5000.H5 IC5000.H6 IC5000.H7 IC5000.H9 IC5000.H10 IC5000.H11 IC5000.J1 IC5000.J2 IC5000.J3 IC5000.J4 IC5000.J5 IC5000.J6 IC5000.J7 IC5000.J8 IC5000.J9 IC5000.J10 IC5000.J11 IC5000.K1 IC5000.K4 IC5000.K6 IC5000.K7 IC5000.K10 IC5000.K11 IC5000.L3 IC5000.L5 IC5000.L6 IC5000.L8 IC5000.L10 IC5000.L11 IC5000.M2 IC5000.M3 IC5000.M4 IC5000.M6 IC5000.M7 IC5000.M8 IC5000.M9 IC5000.M11 IC5000.N4 IC5000.N5 IC5000.N6 IC5000.N7 IC5000.N11 IC5000.P0 IC5000.P1 IC5000.P2 IC5000.P4 IC5000.P7 IC5000.P9 IC5000.P11 IC5000.R0 IC5000.R1 IC5000.R10 IC5000.R11 IC5000.T1 IC5000.T10 IC5000.U1 IC5000.U2 IC5000.U3 IC5000.U4 IC5000.U5 IC5000.U8 IC5000.U9 IC5000.U10 IC6000.1 IC6000.2 IC6000.3 IC6000.4 IC6000.5 IC6000.6 IC6000.13 IC6000.14 IC6000.16 IC6000.19 IC6000.20 IC6000.21 IC6000.22 IC6000.23 IC6000.24 IC6000.MP1 IC6000.MP2 IC6000.MP3 IC6000.MP4
copper on no net:
  other v2: 103.524,83.665 104.524,83.665 105.524,83.665 106.524,83.665 107.524,83.665 108.524,83.665 109.524,83.665 103.524,84.665 104.524,84.665 105.524,84.665 106.524,84.665 107.524,84.665 108.524,84.665 109.524,84.665 103.524,85.665 104.524,85.665 105.524,85.665 106.524,85.665 107.524,85.665 108.524,85.665 109.524,85.665 103.524,86.665 104.524,86.665 105.524,86.665 106.524,86.665 107.524,86.665 108.524,86.665 109.524,86.665 103.524,87.665 104.524,87.665 105.524,87.665 106.524,87.665 107.524,87.665 108.524,87.665 109.524,87.665 103.524,88.665 104.524,88.665 105.524,88.665 106.524,88.665 107.524,88.665 108.524,88.665 109.524,88.665 103.524,89.665 104.524,89.665 105.524,89.665 106.524,89.665 107.524,89.665 108.524,89.665 109.524,89.665

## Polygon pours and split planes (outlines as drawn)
GND on Signal 8 "GND_L08_P001" (solid, remove dead copper, pour order 1): 141.5,106.85 141.5,104.725 149.3,104.725 149.575,105 149.4,105.175 149.4,106.85
+V_SMPS_3V3 on Signal 8 "+V_SMPS_3V3_L08_P000" (solid, remove dead copper, pour order 0): 140.4,104.5 149.2,104.5 149.2,101 140.4,101
+V_SMPS_3V3 on Signal 1 "+V_SMPS_3V3_L01_P004" (solid, remove dead copper, pour order 4): 96.925,90.675 101.525,90.675 101.525,90.2 102.712,90.2 102.712,89.575 96.925,89.575
+V_IN on Power/Signal 6 "+V_IN_L06_P006" (solid, remove dead copper, pour order 6): 86.5,32.1 103.2,32.1 103.2,14.8 99.6,11.2 97,11.2 96.9,11.1 96.9,-0.1 95,-0.1 94.9,-0.2 94.9,10.9 94.5,11.3 89,11.3 86.5,13.8
+V_SMPS_1V8 on Power/Signal 6 "+V_SMPS_1V8_L06_P008" (solid, remove dead copper, pour order 8): 234.8,81.975 254.075,81.975 254.075,73 234.8,73
+V_SMPS_3V3 on Power/Signal 6 "+V_SMPS_3V3_L06_P003" (solid, remove dead copper, pour order 3): 215.1,81.975 234.375,81.975 234.375,73 215.1,73
no net on Layer0 "Default Coverlay 2 Top" (split plane): 203.5,73 194.5,73 194.5,118 203.5,118
no net on Layer0 "Default Coverlay 2 Top" (split plane): 118.5,65.5 118.5,56.5 74.5,56.5 74.5,65.5
no net on Layer0 "Default Coverlay 2 Top" (split plane): 134.5,73 125.5,73 125.5,118 134.5,118
no net on Layer0 "Default Coverlay 2 Top" (split plane): 65.5,4 56.5,4 56.5,49 65.5,49
no net on Layer0 "Default Coverlay 2 Bottom" (split plane): 203.5,73 194.5,73 194.5,118 203.5,118
no net on Layer0 "Default Coverlay 2 Bottom" (split plane): 118.5,65.5 118.5,56.5 74.5,56.5 74.5,65.5
no net on Layer0 "Default Coverlay 2 Bottom" (split plane): 134.5,73 125.5,73 125.5,118 134.5,118
no net on Layer0 "Default Coverlay 2 Bottom" (split plane): 65.5,4 56.5,4 56.5,49 65.5,49
GND on GND (split plane): 165 vertices, not listed, extent -2.99,-2.99 262.99,124.99
GND on GND 7 (split plane): 117.999,56.4 118.028,56.305 118.076,56.216 118.139,56.139 118.216,56.076 118.305,56.028 118.4,55.999 118.5,55.99 124.99,55.99 124.99,-2.99 66.01,-2.99 66.01,4 66.001,4.1 65.972,4.195 65.924,4.284 65.861,4.361 65.784,4.424 65.695,4.472 65.6,4.501 65.5,4.51 65.5,48.49 65.6,48.499 65.695,48.528 65.784,48.576 65.861,48.639 65.924,48.716 65.972,48.805 66.001,48.9 66.01,49 66.01,55.99 74.5,55.99 74.6,55.999 74.695,56.028 74.784,56.076 74.861,56.139 74.924,56.216 74.972,56.305 75.001,56.4 75.01,56.5 117.99,56.5
GND on GND 7 (split plane): 55.99,49 55.999,48.9 56.028,48.805 56.076,48.716 56.139,48.639 56.216,48.576 56.305,48.528 56.4,48.499 56.5,48.49 56.5,4.51 56.4,4.501 56.305,4.472 56.216,4.424 56.139,4.361 56.076,4.284 56.028,4.195 55.999,4.1 55.99,4 55.99,-2.99 -2.99,-2.99 -2.99,55.99 55.99,55.99
GND on GND 7 (split plane): 124.99,118 124.999,117.9 125.028,117.805 125.076,117.716 125.139,117.639 125.216,117.576 125.305,117.528 125.4,117.499 125.5,117.49 125.5,73.51 125.4,73.501 125.305,73.472 125.216,73.424 125.139,73.361 125.076,73.284 125.028,73.195 124.999,73.1 124.99,73 124.99,66.01 118.5,66.01 118.4,66.001 118.305,65.972 118.216,65.924 118.139,65.861 118.076,65.784 118.028,65.695 117.999,65.6 117.99,65.5 75.01,65.5 75.001,65.6 74.972,65.695 74.924,65.784 74.861,65.861 74.784,65.924 74.695,65.972 74.6,66.001 74.5,66.01 66.01,66.01 66.01,124.99 124.99,124.99
GND on GND 7 (split plane): 193.99,118 193.999,117.9 194.028,117.805 194.076,117.716 194.139,117.639 194.216,117.576 194.305,117.528 194.4,117.499 194.5,117.49 194.5,73.51 194.4,73.501 194.305,73.472 194.216,73.424 194.139,73.361 194.076,73.284 194.028,73.195 193.999,73.1 193.99,73 193.99,66.01 135.01,66.01 135.01,73 135.001,73.1 134.972,73.195 134.924,73.284 134.861,73.361 134.784,73.424 134.695,73.472 134.6,73.501 134.5,73.51 134.5,117.49 134.6,117.499 134.695,117.528 134.784,117.576 134.861,117.639 134.924,117.716 134.972,117.805 135.001,117.9 135.01,118 135.01,124.99 193.99,124.99
GND on GND 7 (split plane): 262.99,66.01 204.01,66.01 204.01,73 204.001,73.1 203.972,73.195 203.924,73.284 203.861,73.361 203.784,73.424 203.695,73.472 203.6,73.501 203.5,73.51 203.5,117.49 203.6,117.499 203.695,117.528 203.784,117.576 203.861,117.639 203.924,117.716 203.972,117.805 204.001,117.9 204.01,118 204.01,124.99 262.99,124.99
GND on GND 3 (split plane): 165 vertices, not listed, extent -2.99,-2.99 262.99,124.99

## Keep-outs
Keep-Out Layer:
  rectangle: 193.5,74 204.5,117
  rectangle: 55.5,4.5 66.5,48
  rectangle: 124.5,74 135.5,117
  rectangle: 75.5,55.5 117.5,66.5
  lines w0.254: -2.5,-2.5 -2.5,55.5 55.5,55.5 55.5,48 66.5,48 66.5,55.5 75.5,55.5 75.5,66.5 66.5,66.5 66.5,124.5 124.5,124.5 124.5,117 135.5,117 135.5,124.5 193.5,124.5 193.5,117 204.5,117 204.5,124.5 262.5,124.5 262.5,66.5 204.5,66.5 204.5,74 193.5,74 193.5,66.5 135.5,66.5 135.5,74 124.5,74 124.5,66.5 117.5,66.5 117.5,55.5 124.5,55.5 124.5,-2.5 66.5,-2.5 66.5,4.5 55.5,4.5 55.5,-2.5 -2.5,-2.5

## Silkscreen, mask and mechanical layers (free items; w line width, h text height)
Mechanical 2:
  circle w0.254: c260,69 r1.75
  circle w0.254: c207,69 r1.75
  circle w0.254: c260,122 r1.75
  circle w0.254: c207,122 r1.75
  circle w0.254: c191,69 r1.75
  circle w0.254: c191,122 r1.75
  circle w0.254: c138,69 r1.75
  circle w0.254: c138,122 r1.75
  circle w0.254: c122,122 r1.75
  circle w0.254: c69,122 r1.75
  circle w0.254: c122,69 r1.75
  circle w0.254: c69,69 r1.75
  circle w0.254: c122,53 r1.75
  circle w0.254: c69,53 r1.75
  circle w0.254: c53,53 r1.75
  circle w0.254: c0,53 r1.75
  circle w0.254: c122,0 r1.75
  circle w0.254: c69,0 r1.75
  circle w0.254: c53,0 r1.75
  circle w0.254: c0,0 r1.75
